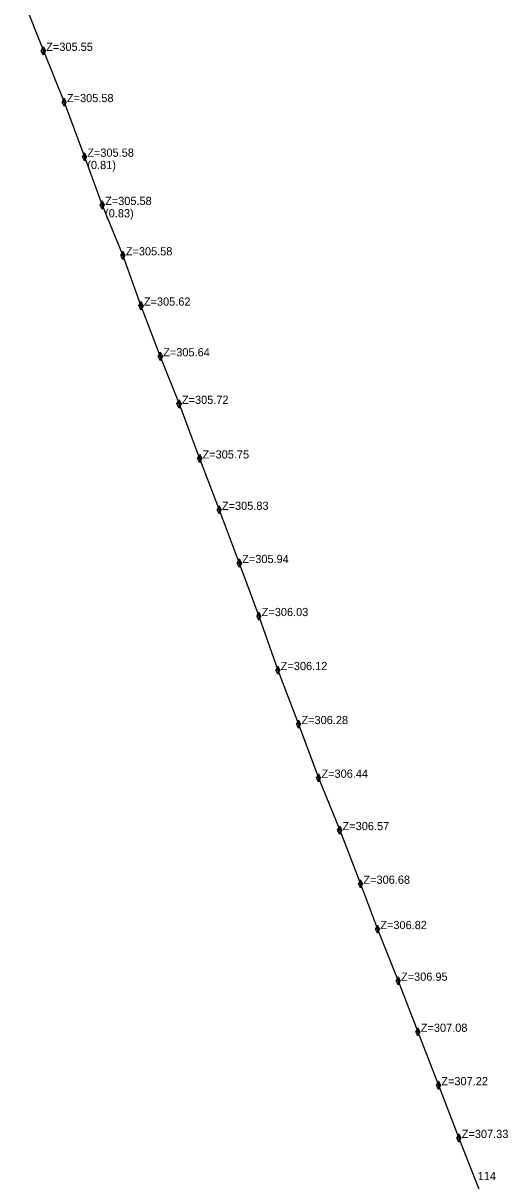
# Model space of a CAD drawing. Extents: x 799271 to 799523, y 67737 to 68184.
# Drawn here: x 799430.1 to 799453.8, y 67793.3 to 67849.8 of the extents above; entities that cross this region are included whole.
import ezdxf

# ---------------------------------------------------------------- set-up
doc = ezdxf.new("R2010")
doc.units = 0
doc.layers.add('PGOC_HTA_CONSTRUIT', color=7, linetype='Continuous')
doc.layers.add('PGOC_PTRL', color=7, linetype='Continuous')

msp = doc.modelspace()

# ---------------------------------------------------------------- linework, layer by layer
at = {"layer": 'PGOC_HTA_CONSTRUIT'}
msp.add_lwpolyline([(799430.135, 67850.913), (799431.122, 67848.416), (799432.132, 67845.917), (799433.125, 67843.253), (799433.994, 67840.901), (799435.004, 67838.446), (799435.886, 67835.995), (799436.829, 67833.524), (799437.743, 67831.207), (799438.748, 67828.546), (799439.697, 67826.043), (799440.684, 67823.45), (799441.635, 67820.863), (799442.565, 67818.231), (799443.576, 67815.598), (799444.553, 67812.982), (799445.584, 67810.429), (799446.6, 67807.814), (799447.424, 67805.606), (799448.435, 67803.087), (799449.401, 67800.599), (799450.403, 67797.995), (799451.399, 67795.423), (799452.389, 67792.892)], dxfattribs=at)
at = {"layer": 'PGOC_PTRL'}
for points in [[(799431.022, 67848.416), (799431.122, 67848.616), (799431.222, 67848.416), (799431.122, 67848.216), (799431.022, 67848.416)], [(799431.222, 67848.416), (799431.122, 67848.416), (799431.022, 67848.416)], [(799431.122, 67848.616), (799431.122, 67848.216)], [(799432.032, 67845.917), (799432.132, 67846.117), (799432.232, 67845.917), (799432.132, 67845.717), (799432.032, 67845.917)], [(799432.232, 67845.917), (799432.132, 67845.917), (799432.032, 67845.917)], [(799432.132, 67846.117), (799432.132, 67845.717)], [(799433.025, 67843.253), (799433.125, 67843.453), (799433.225, 67843.253), (799433.125, 67843.053), (799433.025, 67843.253)], [(799433.225, 67843.253), (799433.125, 67843.253), (799433.025, 67843.253)], [(799433.125, 67843.453), (799433.125, 67843.053)], [(799433.894, 67840.901), (799433.994, 67841.101), (799434.094, 67840.901), (799433.994, 67840.701), (799433.894, 67840.901)], [(799434.094, 67840.901), (799433.994, 67840.901), (799433.894, 67840.901)], [(799433.994, 67841.101), (799433.994, 67840.701)], [(799434.904, 67838.446), (799435.004, 67838.646), (799435.104, 67838.446), (799435.004, 67838.246), (799434.904, 67838.446)], [(799435.004, 67838.646), (799435.004, 67838.246)], [(799435.104, 67838.446), (799435.004, 67838.446), (799434.904, 67838.446)], [(799435.786, 67835.995), (799435.886, 67836.195), (799435.986, 67835.995), (799435.886, 67835.795), (799435.786, 67835.995)], [(799435.986, 67835.995), (799435.886, 67835.995), (799435.786, 67835.995)], [(799435.886, 67836.195), (799435.886, 67835.795)], [(799436.729, 67833.524), (799436.829, 67833.724), (799436.929, 67833.524), (799436.829, 67833.324), (799436.729, 67833.524)], [(799436.929, 67833.524), (799436.829, 67833.524), (799436.729, 67833.524)], [(799436.829, 67833.724), (799436.829, 67833.324)], [(799437.643, 67831.207), (799437.743, 67831.407), (799437.843, 67831.207), (799437.743, 67831.007), (799437.643, 67831.207)], [(799437.843, 67831.207), (799437.743, 67831.207), (799437.643, 67831.207)], [(799437.743, 67831.407), (799437.743, 67831.007)], [(799438.648, 67828.546), (799438.748, 67828.746), (799438.848, 67828.546), (799438.748, 67828.346), (799438.648, 67828.546)], [(799438.848, 67828.546), (799438.748, 67828.546), (799438.648, 67828.546)], [(799438.748, 67828.746), (799438.748, 67828.346)], [(799439.597, 67826.043), (799439.697, 67826.243), (799439.797, 67826.043), (799439.697, 67825.843), (799439.597, 67826.043)], [(799439.697, 67826.243), (799439.697, 67825.843)], [(799439.797, 67826.043), (799439.697, 67826.043), (799439.597, 67826.043)], [(799440.584, 67823.45), (799440.684, 67823.65), (799440.784, 67823.45), (799440.684, 67823.25), (799440.584, 67823.45)], [(799440.784, 67823.45), (799440.684, 67823.45), (799440.584, 67823.45)], [(799440.684, 67823.65), (799440.684, 67823.25)], [(799441.535, 67820.863), (799441.635, 67821.063), (799441.735, 67820.863), (799441.635, 67820.663), (799441.535, 67820.863)], [(799441.635, 67821.063), (799441.635, 67820.663)], [(799441.735, 67820.863), (799441.635, 67820.863), (799441.535, 67820.863)], [(799442.465, 67818.231), (799442.565, 67818.431), (799442.665, 67818.231), (799442.565, 67818.031), (799442.465, 67818.231)], [(799442.665, 67818.231), (799442.565, 67818.231), (799442.465, 67818.231)], [(799442.565, 67818.431), (799442.565, 67818.031)], [(799443.476, 67815.598), (799443.576, 67815.798), (799443.676, 67815.598), (799443.576, 67815.398), (799443.476, 67815.598)], [(799443.676, 67815.598), (799443.576, 67815.598), (799443.476, 67815.598)], [(799443.576, 67815.798), (799443.576, 67815.398)], [(799444.453, 67812.982), (799444.553, 67813.182), (799444.653, 67812.982), (799444.553, 67812.782), (799444.453, 67812.982)], [(799444.553, 67813.182), (799444.553, 67812.782)], [(799444.653, 67812.982), (799444.553, 67812.982), (799444.453, 67812.982)], [(799445.484, 67810.429), (799445.584, 67810.629), (799445.684, 67810.429), (799445.584, 67810.229), (799445.484, 67810.429)], [(799445.684, 67810.429), (799445.584, 67810.429), (799445.484, 67810.429)], [(799445.584, 67810.629), (799445.584, 67810.229)], [(799446.5, 67807.814), (799446.6, 67808.014), (799446.7, 67807.814), (799446.6, 67807.614), (799446.5, 67807.814)], [(799446.7, 67807.814), (799446.6, 67807.814), (799446.5, 67807.814)], [(799446.6, 67808.014), (799446.6, 67807.614)], [(799447.324, 67805.606), (799447.424, 67805.806), (799447.524, 67805.606), (799447.424, 67805.406), (799447.324, 67805.606)], [(799447.424, 67805.806), (799447.424, 67805.406)], [(799447.524, 67805.606), (799447.424, 67805.606), (799447.324, 67805.606)], [(799448.335, 67803.087), (799448.435, 67803.287), (799448.535, 67803.087), (799448.435, 67802.887), (799448.335, 67803.087)], [(799448.535, 67803.087), (799448.435, 67803.087), (799448.335, 67803.087)], [(799448.435, 67803.287), (799448.435, 67802.887)], [(799449.301, 67800.599), (799449.401, 67800.799), (799449.501, 67800.599), (799449.401, 67800.399), (799449.301, 67800.599)], [(799449.401, 67800.799), (799449.401, 67800.399)], [(799449.501, 67800.599), (799449.401, 67800.599), (799449.301, 67800.599)], [(799450.303, 67797.995), (799450.403, 67798.195), (799450.503, 67797.995), (799450.403, 67797.795), (799450.303, 67797.995)], [(799450.503, 67797.995), (799450.403, 67797.995), (799450.303, 67797.995)], [(799450.403, 67798.195), (799450.403, 67797.795)], [(799451.299, 67795.423), (799451.399, 67795.623), (799451.499, 67795.423), (799451.399, 67795.223), (799451.299, 67795.423)], [(799451.399, 67795.623), (799451.399, 67795.223)], [(799451.499, 67795.423), (799451.399, 67795.423), (799451.299, 67795.423)]]:
    msp.add_lwpolyline(points, dxfattribs=at)

# ---------------------------------------------------------------- texts
for s, p in [('Z=305.55', (799431.262, 67848.416)), ('Z=305.58', (799432.272, 67845.917)), ('Z=305.58', (799433.265, 67843.253)), ('(0.81)', (799433.265, 67842.653)), ('Z=305.58', (799434.134, 67840.901)), ('(0.83)', (799434.134, 67840.301)), ('Z=305.58', (799435.144, 67838.446)), ('Z=305.62', (799436.026, 67835.995)), ('Z=305.64', (799436.969, 67833.524)), ('Z=305.72', (799437.883, 67831.207)), ('Z=305.75', (799438.888, 67828.546)), ('Z=305.83', (799439.837, 67826.043)), ('Z=305.94', (799440.824, 67823.45)), ('Z=306.03', (799441.775, 67820.863)), ('Z=306.12', (799442.705, 67818.231)), ('Z=306.28', (799443.716, 67815.598)), ('Z=306.44', (799444.693, 67812.982)), ('Z=306.57', (799445.724, 67810.429)), ('Z=306.68', (799446.74, 67807.814)), ('Z=306.82', (799447.564, 67805.606)), ('Z=306.95', (799448.575, 67803.087)), ('Z=307.08', (799449.541, 67800.599)), ('Z=307.22', (799450.543, 67797.995)), ('Z=307.33', (799451.539, 67795.423)), ('114', (799452.319, 67793.372))]:
    msp.add_text(s, height=0.4, dxfattribs=at).set_placement(p)

doc.saveas('drawing.dxf')
